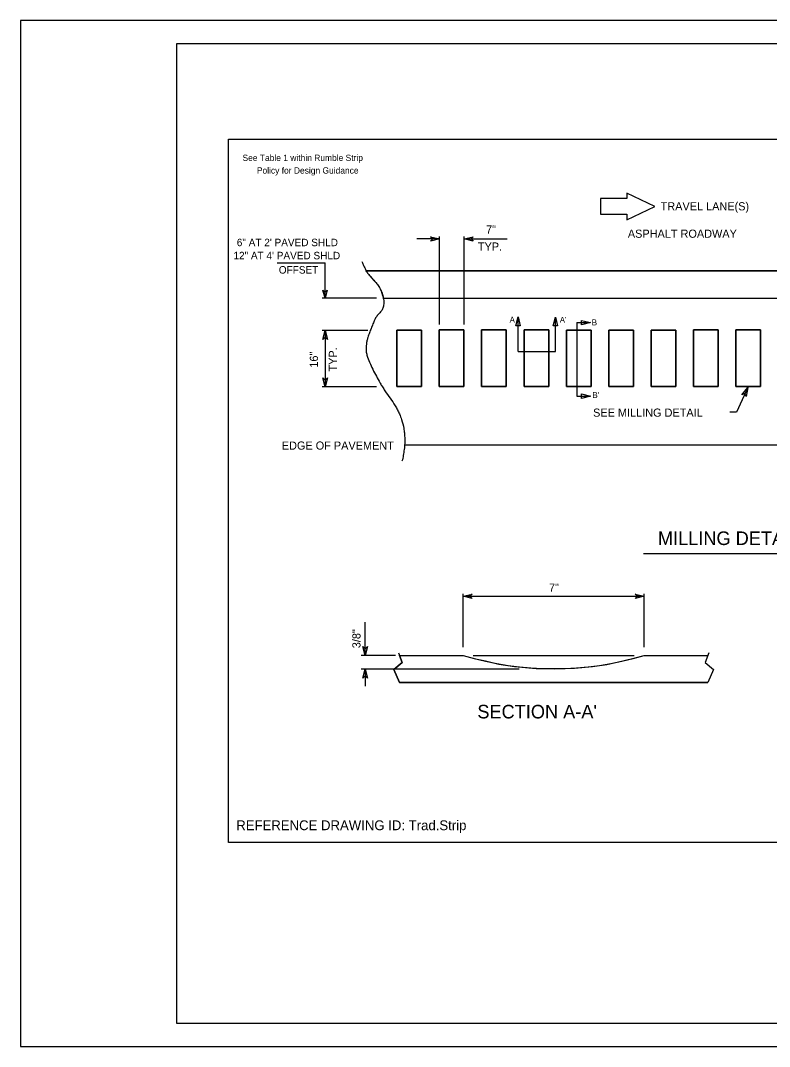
# Model space of a CAD drawing. Extents: x 1994737 to 2001433, y 527447 to 529360.
# Drawn here: x 1997029 to 1997988, y 527799 to 529114 of the extents above; entities that cross this region are included whole.
import ezdxf

# ---------------------------------------------------------------- set-up
doc = ezdxf.new("R2010")
doc.units = 0
for name, color, linetype in [('Default', 7, 'Continuous'), ('GSBWFILL', 7, 'Continuous'), ('Old_Level_33', 7, 'Continuous'), ('Prop Sign E Yield Sign Ahead CELL', 7, 'Continuous'), ('Prop Support Two', 7, 'Continuous')]:
    doc.layers.add(name, color=color, linetype=linetype)

# ---------------------------------------------------------------- blocks, each defined once
blk = doc.blocks.new('DTF')
at = {"layer": 'Default'}
for p, q in [((-10.33475, 4.8755), (-10.33625, 2.90475)), ((0, 0), (-10.33475, 4.8755)), ((-19.936, 2.9115), (-19.9395, -2.8845)), ((-10.33625, 2.90475), (-19.936, 2.9115)), ((-10.34125, -4.8615), (0, 0)), ((-19.9395, -2.8845), (-10.3405, -2.891)), ((-10.3405, -2.891), (-10.34125, -4.8615))]:
    blk.add_line(p, q, dxfattribs=at)
blk = doc.blocks.new('TERM2')
at = {"layer": 'Default'}
for p, q in [((-6.25, 1.563), (0, 0)), ((-4.687, 0), (-6.25, 1.563)), ((0, 0), (-6.25, -1.563)), ((-6.25, -1.563), (-4.687, 0))]:
    blk.add_line(p, q, dxfattribs=at)

msp = doc.modelspace()

# ---------------------------------------------------------------- linework, layer by layer
at = {"layer": 'Default'}
for p, q in [((1997565.1, 528834.2), (1997536.2, 528834.2)), ((1997565.1, 528724.6), (1997565.1, 528837.5)), ((1997596.7, 528724.5), (1997596.7, 528837.5)), ((1997596.7, 528834.2), (1997651.7, 528834.2)), ((1997357.3, 528803.5), (1997418.5, 528803.5)), ((1997418.5, 528758.1), (1997418.5, 528803.5)), ((1997470.2, 528793.5), (1998277.6, 528793.5)), ((1998277.3, 528793.5), (1997471.1, 528793.5)), ((1997484.5, 528758.1), (1997414.8, 528758.1)), ((1997492.7, 528758.5), (1998255.9, 528758.5)), ((1997493.1, 528758.5), (1998255.2, 528758.5)), ((1997665.6, 528689.9), (1997665.6, 528734.3)), ((1997713.5, 528689.9), (1997713.5, 528734.1)), ((1997473.1, 528717), (1997414.8, 528717)), ((1997418.7, 528717), (1997418.7, 528644.6)), ((1997740.8, 528727.1), (1997740.8, 528632.7)), ((1997741, 528727.1), (1997757.4, 528727.1)), ((1997665.6, 528689.9), (1997713.5, 528689.9)), ((1997484.5, 528644.6), (1997414.8, 528644.6)), ((1997959.7, 528643.9), (1997945.4, 528612.1)), ((1997740.8, 528632.7), (1997757.6, 528632.7)), ((1997945.5, 528612.1), (1997936.7, 528612.1)), ((1997520.3, 528570.4), (1998228.2, 528570.4)), ((1997826.2, 528431.2), (1998088.3, 528431.2)), ((1997595.3, 528311.1), (1997595.3, 528379.5)), ((1997595.3, 528376.3), (1997827.3, 528376.3)), ((1997827.3, 528311.1), (1997827.3, 528379.5)), ((1997469.8, 528300.5), (1997469.8, 528343.3)), ((1997508.9, 528300.5), (1997464.7, 528300.5)), ((1997512.7, 528304), (1997517.3, 528291.6)), ((1997514, 528300.5), (1997595.3, 528300.5)), ((1997608.2, 528300.5), (1997814.4, 528300.5)), ((1997827.3, 528300.5), (1997908.6, 528300.5)), ((1997909.9, 528304), (1997905.4, 528291.6)), ((1997666.9, 528283.1), (1997464.7, 528283.1)), ((1997469.8, 528283.1), (1997469.8, 528261.1)), ((1997517.3, 528291.6), (1997506.6, 528282.3)), ((1997506.6, 528282.3), (1997514, 528265.7)), ((1997905.4, 528291.6), (1997916, 528282.3)), ((1997916, 528282.3), (1997908.6, 528265.7)), ((1997514, 528265.7), (1997908.6, 528265.7))]:
    msp.add_line(p, q, dxfattribs=at)
for points in [[(1997294.9, 528962), (1998712.7, 528962), (1998712.7, 528061), (1997294.9, 528061)], [(1997662.7, 528722.9), (1997665.6, 528734.3), (1997668.5, 528722.9)], [(1997710.6, 528722.7), (1997713.5, 528734.1), (1997716.3, 528722.7)], [(1997746.8, 528729.9), (1997758.2, 528727.1), (1997746.8, 528724.2)], [(1997510.4, 528717.4), (1997542, 528717.4), (1997542, 528645.1), (1997510.4, 528645.1)], [(1997542, 528645.1), (1997510.4, 528645.1), (1997510.4, 528717.4), (1997542, 528717.4)], [(1997564.7, 528717.6), (1997596.3, 528717.6), (1997596.3, 528645.2), (1997564.7, 528645.2)], [(1997564.7, 528717.6), (1997596.3, 528717.6), (1997596.3, 528645.2), (1997564.7, 528645.2)], [(1997619, 528717.6), (1997650.6, 528717.6), (1997650.6, 528645.2), (1997619, 528645.2)], [(1997619, 528645.2), (1997650.6, 528645.2), (1997650.6, 528717.6), (1997619, 528717.6)], [(1997673.3, 528717.6), (1997704.9, 528717.6), (1997704.9, 528645.2), (1997673.3, 528645.2)], [(1997673.3, 528717.6), (1997704.9, 528717.6), (1997704.9, 528645.2), (1997673.3, 528645.2)], [(1997727.5, 528717.5), (1997759.1, 528717.5), (1997759.1, 528645.1), (1997727.5, 528645.1)], [(1997727.5, 528645.1), (1997759.1, 528645.1), (1997759.1, 528717.5), (1997727.5, 528717.5)], [(1997781.8, 528717.5), (1997813.4, 528717.5), (1997813.4, 528645.1), (1997781.8, 528645.1)], [(1997781.8, 528717.5), (1997813.4, 528717.5), (1997813.4, 528645.1), (1997781.8, 528645.1)], [(1997836.1, 528717.5), (1997867.7, 528717.5), (1997867.7, 528645.1), (1997836.1, 528645.1)], [(1997836.1, 528717.5), (1997867.7, 528717.5), (1997867.7, 528645.1), (1997836.1, 528645.1)], [(1997890.3, 528717.7), (1997922, 528717.7), (1997922, 528645.3), (1997890.3, 528645.3)], [(1997890.3, 528717.7), (1997922, 528717.7), (1997922, 528645.3), (1997890.3, 528645.3)], [(1997944.6, 528717.7), (1997976.2, 528717.7), (1997976.2, 528645.3), (1997944.6, 528645.3)], [(1997944.6, 528717.7), (1997976.2, 528717.7), (1997976.2, 528645.3), (1997944.6, 528645.3)], [(1997746.9, 528635.6), (1997758.3, 528632.7), (1997746.9, 528629.9)], [(1997827.3, 528300.5), (1997908.6, 528300.5), (1997905.4, 528291.6), (1997916, 528282.3), (1997908.6, 528265.7), (1997514, 528265.7), (1997506.6, 528282.3), (1997517.3, 528291.6), (1997514, 528300.5), (1997595.3, 528300.5), (1997611, 528296), (1997624, 528293.4), (1997640.8, 528289.5), (1997661, 528286.5), (1997689, 528283.9), (1997711.9, 528283.5), (1997737.7, 528284.4), (1997761, 528286.5), (1997779.5, 528289.1), (1997799.8, 528293.4), (1997815.7, 528297.3), (1997827.3, 528300.5)]]:
    msp.add_lwpolyline(points, close=True, dxfattribs=at)
for points in [[(1997510.4, 528645.1), (1997542, 528645.1), (1997542, 528717.4), (1997510.4, 528717.4), (1997510.4, 528645.1)], [(1997564.7, 528645.2), (1997596.3, 528645.2), (1997596.3, 528717.6), (1997564.7, 528717.6), (1997564.7, 528645.2)], [(1997619, 528645.2), (1997650.6, 528645.2), (1997650.6, 528717.6), (1997619, 528717.6), (1997619, 528645.2)], [(1997673.3, 528645.2), (1997704.9, 528645.2), (1997704.9, 528717.6), (1997673.3, 528717.6), (1997673.3, 528645.2)], [(1997727.5, 528645.1), (1997759.1, 528645.1), (1997759.1, 528717.5), (1997727.5, 528717.5), (1997727.5, 528645.1)], [(1997781.8, 528645.1), (1997813.4, 528645.1), (1997813.4, 528717.5), (1997781.8, 528717.5), (1997781.8, 528645.1)], [(1997836.1, 528645.1), (1997867.7, 528645.1), (1997867.7, 528717.5), (1997836.1, 528717.5), (1997836.1, 528645.1)], [(1997890.3, 528645.3), (1997922, 528645.3), (1997922, 528717.7), (1997890.3, 528717.7), (1997890.3, 528645.3)], [(1997944.6, 528645.3), (1997976.2, 528645.3), (1997976.2, 528717.7), (1997944.6, 528717.7), (1997944.6, 528645.3)]]:
    msp.add_lwpolyline(points, dxfattribs=at)
msp.add_arc((1997711.3, 528689.6), 406, 253.4, 286.5999, dxfattribs=at)
for points in [[(1997465.7, 528805.2), (1997466.4, 528803.4), (1997468.3, 528799.3), (1997470.2, 528795.2), (1997472.1, 528791.7), (1997474.4, 528788.5), (1997479.6, 528782.6), (1997484.8, 528776.8), (1997488.1, 528772.1), (1997489, 528770.4), (1997491.5, 528764.7), (1997493.1, 528758.5), (1997493.7, 528752.4), (1997493.5, 528749.4), (1997493, 528746.6), (1997491, 528742.6), (1997487.9, 528738.8), (1997484.6, 528735), (1997482.1, 528730.8), (1997479.8, 528725.3), (1997477.5, 528719.6), (1997475.3, 528713.9), (1997474.3, 528711), (1997473.3, 528708), (1997472.2, 528703.7), (1997471.4, 528699.3), (1997471.1, 528695), (1997471.1, 528690.7), (1997471.5, 528687.9), (1997472.2, 528685.2), (1997475.5, 528676.2), (1997479.6, 528667.2), (1997489, 528649.6), (1997492, 528644.5), (1997495.2, 528639.6), (1997501.8, 528630.1), (1997508.3, 528620.4), (1997511.2, 528615.3), (1997512.5, 528612.6), (1997513.8, 528609.9), (1997516.5, 528602.7), (1997519.3, 528591.4), (1997520.1, 528585.6), (1997520.5, 528579.9), (1997520.5, 528572.1), (1997519.8, 528564.4), (1997518.7, 528556.8), (1997517, 528549.4)], [(1997471.1, 528793.5), (1997473, 528790.4), (1997475.3, 528787.4), (1997480.2, 528782), (1997485, 528776.5), (1997487.2, 528773.6), (1997489, 528770.4), (1997493.1, 528758.5)]]:
    msp.add_spline(points, degree=3, dxfattribs=at)
at = {"layer": 'GSBWFILL'}
for p, q in [((1999041.1, 529114.1), (1997028.6, 529114.1)), ((1997028.6, 529114.1), (1997028.6, 527799.4)), ((1997028.6, 527799.4), (1999041.1, 527799.4))]:
    msp.add_line(p, q, dxfattribs=at)
at = {"layer": 'Old_Level_33'}
msp.add_line((1997229.3, 529084.2), (1997229.3, 529084.2), dxfattribs=at)
at = {"layer": 'Prop Sign E Yield Sign Ahead CELL'}
msp.add_lwpolyline([(1999020.8, 529084.2), (1997228.2, 529084.2), (1997228.2, 527829.3), (1999020.8, 527829.3)], close=True, dxfattribs=at)
at = {"layer": 'Prop Support Two'}
msp.add_line((1997028.6, 527799.4), (1997028.6, 527799.4), dxfattribs=at)

# ---------------------------------------------------------------- block references
at = {"layer": 'Default', "xscale": 3.4793784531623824, "yscale": 3.4793784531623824}
msp.add_blockref('DTF', (1997840.7, 528875.8), dxfattribs=at)
at = {"layer": 'Default'}
for p, xscale, yscale, rotation in [((1997565.1, 528834.2), 1.8556685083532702, 1.8556685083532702, 2.7372046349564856e-11), ((1997596.7, 528834.2), 1.8556685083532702, 1.8556685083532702, -179.99999999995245), ((1997418.5, 528758.1), 1.7040114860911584, 1.7040114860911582, -89.99999999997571), ((1997418.7, 528717), 1.8556685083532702, 1.8556685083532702, 89.99999999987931), ((1997418.7, 528644.6), 1.8556685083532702, 1.8556685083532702, -90.0000000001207), ((1997959.7, 528643.9), 1.8556685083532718, 1.8556685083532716, 65.81937702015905), ((1997595.3, 528376.3), 1.8556685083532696, 1.85566850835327, 179.99984077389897), ((1997827.3, 528376.3), 1.8556685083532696, 1.85566850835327, -0.0001592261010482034), ((1997469.8, 528300.5), 1.855668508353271, 1.8556685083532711, -89.99968490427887), ((1997469.8, 528283.1), 1.8556685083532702, 1.8556685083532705, 89.99993359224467)]:
    msp.add_blockref('TERM2', p, dxfattribs=dict(at, xscale=xscale, yscale=yscale, rotation=rotation))

# ---------------------------------------------------------------- texts
for s, height, rotation, p in [('See Table 1 within Rumble Strip', 8.074, 360, (1997312.8, 528934.1)), ('Policy for Design Guidance', 8.074, 360, (1997331.2, 528917.9)), ('TRAVEL LANE(S)', 10.438, 360, (1997848.2, 528870.8)), ('7"', 10.44, 360, (1997624.6, 528841)), ('6" AT 2\' PAVED SHLD', 9.585, 360, (1997305.5, 528824.9)), ('ASPHALT ROADWAY', 10.438, 360, (1997806.2, 528835.7)), ('TYP.', 10.44, 360, (1997614.2, 528819.2)), ('12" AT 4\' PAVED SHLD', 9.585, 360, (1997301.2, 528808.1)), ('OFFSET', 9.59, 360, (1997359.3, 528789.8)), ('A', 7.61, 0, (1997654.8, 528726.9)), ("A'", 7.61, 0, (1997719, 528726.7)), ('B', 7.61, 0, (1997760, 528723.4)), ('16"', 10.44, 90, (1997409.4, 528669.3)), ('TYP.', 10.44, 90, (1997433.7, 528664.3)), ("B'", 7.61, 0, (1997760.8, 528630.4)), ('SEE MILLING DETAIL', 10.438, 360, (1997761.7, 528606.4)), ('EDGE OF PAVEMENT', 10.438, 360, (1997363.1, 528564.2)), ('MILLING DETAIL:', 17.397, 0, (1997844.7, 528442)), ('7"', 10.44, 0, (1997705.2, 528382.2)), ('3/8"', 10.44, 90.0002, (1997463.9, 528309.8)), ("SECTION A-A'", 17.397, 0, (1997613.5, 528219.8)), ('REFERENCE DRAWING ID: Trad.Strip', 12.592, 0, (1997304.8, 528076.6))]:
    msp.add_text(s, height=height, rotation=rotation, dxfattribs=at).set_placement(p)

doc.saveas('drawing.dxf')
